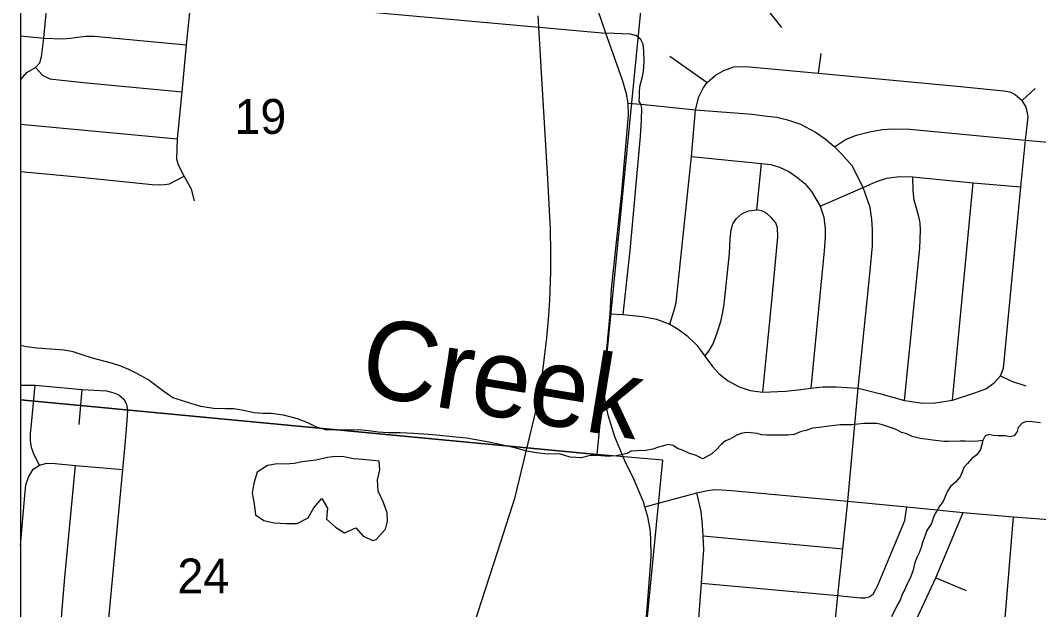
# Model space of a CAD drawing. Extents: x 0 to 34, y 0 to 22.
# Drawn here: x 1.912 to 3.134, y 16.316 to 17.023 of the extents above; entities that cross this region are included whole.
import ezdxf

# ---------------------------------------------------------------- set-up
doc = ezdxf.new("R2010")
doc.units = 0
for name, color, linetype in [('GM_X_City_Street', 7, 'Continuous'), ('GM_X_Corporation', 7, 'Continuous'), ('GM_X_County_Road', 7, 'Continuous'), ('GM_X_Minor_Lake', 7, 'Continuous'), ('GM_X_Minor_River', 7, 'Continuous'), ('GM_X_Minor_River_Text', 7, 'Continuous'), ('GM_X_Rail_Line', 7, 'Continuous'), ('GM_X_Section_Text', 7, 'Continuous')]:
    doc.layers.add(name, color=color, linetype=linetype)

msp = doc.modelspace()

# ---------------------------------------------------------------- linework, layer by layer
at = {"layer": 'GM_X_City_Street'}
for p, q in [((2.6913, 16.98), (2.7361, 16.9485)), ((2.8697, 16.9597), (2.8731, 16.9833)), ((3.1141, 16.927), (3.13, 16.9414)), ((1.9119, 16.8983), (2.1004, 16.8808)), ((2.7957, 16.7958), (2.8014, 16.8511)), ((3.0306, 16.5674), (3.0555, 16.8282)), ((1.9823, 16.5381), (1.986, 16.5803)), ((2.7314, 16.4048), (2.8989, 16.3891)), ((3.0105, 16.3541), (3.0471, 16.339))]:
    msp.add_line(p, q, dxfattribs=at)
for points in [[(2.8256, 17.0144), (2.8057, 17.0397), (2.7927, 17.0541), (2.7848, 17.0643), (2.7775, 17.0752), (2.7735, 17.0861), (2.7724, 17.097), (2.7742, 17.1209), (2.7788, 17.1692), (2.7815, 17.1984), (2.7824, 17.2213), (2.782, 17.2298), (2.7793, 17.2429), (2.7749, 17.2575), (2.7707, 17.2683), (2.7612, 17.286), (2.7527, 17.2976), (2.7471, 17.304), (2.7397, 17.3099), (2.729, 17.3149), (2.7152, 17.3176)], [(1.9119, 16.9515), (1.9196, 16.9603), (1.9301, 16.9665), (1.9352, 16.9719), (1.9372, 16.9792), (1.9401, 17.0018), (1.9462, 17.0651), (1.9467, 17.0701)], [(2.121, 16.8066), (2.1174, 16.8205), (2.1084, 16.836), (2.1016, 16.8491), (2.0995, 16.8563), (2.1004, 16.8808), (2.106, 16.9372), (2.1111, 16.9937), (2.1173, 17.0524), (2.1184, 17.0661)], [(2.0384, 17.0604), (2.0606, 17.0586), (2.1173, 17.0524), (2.343, 17.0322), (2.6147, 17.0077)], [(1.9119, 17.0045), (1.9401, 17.0018), (1.9627, 17.0008), (1.9721, 17.0017), (1.9802, 17.0027), (1.9907, 17.0039), (2.0004, 17.004), (2.1111, 16.9937)], [(2.6355, 16.6703), (2.6436, 16.7471), (2.6563, 16.8838), (2.6575, 16.9032), (2.6579, 16.9177), (2.6565, 16.9224), (2.6545, 16.9258), (2.6548, 16.9326), (2.6549, 16.9364), (2.6553, 16.9436), (2.6586, 16.9555), (2.6599, 16.9621), (2.6603, 16.9671), (2.6604, 16.9734), (2.6601, 16.9861), (2.6594, 16.9945), (2.6564, 17), (2.6513, 17.0045), (2.6443, 17.0065), (2.6147, 17.0077)], [(1.9301, 16.9665), (1.9386, 16.9571), (1.9472, 16.9527), (1.9873, 16.9484), (2.106, 16.9372)], [(2.7223, 16.9158), (2.7262, 16.9313), (2.7315, 16.9415), (2.7361, 16.9485), (2.746, 16.9571), (2.756, 16.9628), (2.7683, 16.9672), (2.7822, 16.9676), (2.8697, 16.9597), (3.0401, 16.9435), (3.0922, 16.9386), (3.0994, 16.9371), (3.106, 16.9341), (3.1141, 16.927)], [(3.0882, 16.5966), (3.0918, 16.6056), (3.0933, 16.622), (3.1127, 16.8233), (3.1184, 16.8792), (3.1208, 16.8999), (3.1214, 16.9074), (3.1208, 16.912), (3.1186, 16.9195), (3.1141, 16.927)], [(2.6415, 16.9235), (2.6565, 16.9224), (2.7223, 16.9158), (2.79, 16.9103), (2.8083, 16.9081), (2.8196, 16.9069), (2.8326, 16.9038), (2.848, 16.8985), (2.866, 16.8889), (2.8778, 16.881), (2.8881, 16.8721)], [(2.6915, 16.6584), (2.6967, 16.6753), (2.699, 16.6846), (2.7174, 16.8597), (2.7223, 16.9158)], [(2.8881, 16.8721), (2.8889, 16.8714), (2.9022, 16.8801), (2.9154, 16.8852), (2.9311, 16.8893), (2.9465, 16.8919), (2.9589, 16.8928), (2.9794, 16.8926), (3.1184, 16.8792), (3.1496, 16.8764)], [(2.8103, 16.1372), (2.8113, 16.1389), (2.8751, 16.2416), (2.8796, 16.2493), (2.8838, 16.2589), (2.8875, 16.276), (2.8931, 16.333), (2.8989, 16.3891), (2.9049, 16.4462), (2.9174, 16.5819), (2.9313, 16.7186), (2.934, 16.7443), (2.9345, 16.7527), (2.9348, 16.7723), (2.9339, 16.7843), (2.9317, 16.7986), (2.9235, 16.8227), (2.9101, 16.8483), (2.897, 16.8632), (2.8889, 16.8714)], [(2.7174, 16.8597), (2.8014, 16.8511), (2.8127, 16.8499), (2.8228, 16.8467), (2.834, 16.8417), (2.8433, 16.8353), (2.8532, 16.8271), (2.8613, 16.8179), (2.8717, 16.8003), (2.876, 16.7868), (2.8778, 16.7728), (2.8779, 16.7628), (2.8765, 16.7467), (2.8607, 16.5818)], [(1.9119, 16.8417), (1.9765, 16.8358), (2.0701, 16.8262), (2.0794, 16.8257), (2.0854, 16.826), (2.0907, 16.827), (2.1084, 16.836)], [(2.8717, 16.8003), (2.9235, 16.8227), (2.9396, 16.8297), (2.9517, 16.8337), (2.9672, 16.8357), (2.9832, 16.8351), (3.0555, 16.8282), (3.1127, 16.8233)], [(2.9729, 16.567), (2.9913, 16.7496), (2.9921, 16.7714), (2.992, 16.7797), (2.9902, 16.7878), (2.988, 16.796), (2.9847, 16.8074), (2.9836, 16.819), (2.9832, 16.8351)], [(2.7332, 16.6203), (2.7381, 16.6263), (2.7434, 16.6351), (2.7483, 16.648), (2.7526, 16.6618), (2.7546, 16.6708), (2.7566, 16.6825), (2.7628, 16.7434), (2.7639, 16.761), (2.7649, 16.7717), (2.7669, 16.7789), (2.7709, 16.7851), (2.7781, 16.7912), (2.7861, 16.7945), (2.7957, 16.7958)], [(2.8031, 16.5768), (2.8144, 16.6944), (2.8211, 16.7635), (2.8207, 16.774), (2.8186, 16.7803), (2.8131, 16.7866), (2.8079, 16.7912), (2.8024, 16.7941), (2.7957, 16.7958)], [(2.6199, 16.6708), (2.6355, 16.6703), (2.6587, 16.6676), (2.6754, 16.6644), (2.6915, 16.6584), (2.7015, 16.6524), (2.712, 16.6445), (2.7237, 16.6332), (2.7332, 16.6203), (2.7424, 16.6077), (2.7501, 16.5994), (2.7605, 16.5911), (2.7745, 16.5833), (2.7877, 16.5788), (2.8031, 16.5768), (2.8303, 16.5782), (2.8486, 16.5802), (2.8607, 16.5818), (2.8748, 16.5832), (2.8911, 16.5835), (2.9174, 16.5819), (2.9445, 16.5748), (2.9729, 16.567), (2.9923, 16.5641), (3.0073, 16.5639), (3.0306, 16.5674), (3.0576, 16.576), (3.0707, 16.5811), (3.0807, 16.5881), (3.0882, 16.5966)], [(3.0882, 16.5966), (3.1014, 16.5901), (3.1185, 16.5845)], [(1.9119, 16.5852), (1.9123, 16.5853), (1.9296, 16.5852), (1.986, 16.5803), (2.0154, 16.5785), (2.024, 16.5763), (2.0301, 16.5736), (2.0366, 16.568)], [(1.9348, 16.4894), (1.9283, 16.5019), (1.9254, 16.5107), (1.924, 16.5191), (1.9241, 16.5274), (1.9252, 16.5387), (1.9296, 16.5852)], [(1.9901, 15.9301), (2, 16.0388), (2.0032, 16.0719), (2.0147, 16.2007), (2.0176, 16.2342), (2.0174, 16.2504), (2.0164, 16.2703), (2.0165, 16.2881), (2.0348, 16.4843), (2.0375, 16.5136), (2.0395, 16.5378), (2.0406, 16.5484), (2.0409, 16.5555), (2.0396, 16.5621), (2.0366, 16.568)], [(1.9119, 16.3931), (1.9174, 16.453), (1.9185, 16.4656), (1.9217, 16.4748), (1.9273, 16.4845), (1.9348, 16.4894)], [(1.9119, 16.259), (1.9314, 16.2618), (1.9418, 16.2644), (1.9491, 16.2683), (1.9547, 16.2736), (1.9587, 16.281), (1.9601, 16.2897), (1.962, 16.3167), (1.9653, 16.3546), (1.9779, 16.4891)], [(1.9348, 16.4894), (1.9437, 16.4918), (1.9535, 16.4912), (1.9779, 16.4891), (2.0348, 16.4843)], [(2.6613, 16.4392), (2.7238, 16.4563), (2.7365, 16.4591), (2.7463, 16.4601), (2.7539, 16.4597), (2.7654, 16.4589), (2.7874, 16.4569), (2.9049, 16.4462), (2.9759, 16.4395), (3.0434, 16.4327), (3.1038, 16.4274), (3.1408, 16.4245), (3.1532, 16.4228), (3.1606, 16.4208), (3.1756, 16.4168), (3.405, 16.3956), (3.4416, 16.3923), (3.4637, 16.3923), (3.5, 16.3912), (3.5347, 16.388), (3.6039, 16.383)], [(2.7243, 16.2806), (2.7249, 16.2895), (2.7294, 16.3479), (2.7311, 16.3723), (2.732, 16.388), (2.7314, 16.4048), (2.7304, 16.4173), (2.7289, 16.4338), (2.7238, 16.4563)], [(2.7294, 16.3479), (2.8931, 16.333), (2.9203, 16.3302), (2.9258, 16.3304), (2.9305, 16.3314), (2.9356, 16.3348), (2.9381, 16.3397), (2.9413, 16.3464), (2.9733, 16.4229), (2.9759, 16.4395)], [(2.8381, 16.0606), (2.8689, 16.1125), (2.9269, 16.2052), (2.9536, 16.2499), (2.9864, 16.302), (3.0105, 16.3541), (3.0434, 16.4327)], [(3.0573, 15.9654), (3.0618, 15.9752), (3.0642, 15.9847), (3.0676, 16.0257), (3.0859, 16.2088), (3.1038, 16.4274)]]:
    msp.add_lwpolyline(points, dxfattribs=at)
at = {"layer": 'GM_X_Corporation'}
for points in [[(1.9119, 21.1059), (1.9119, 14.3059)], [(1.9119, 21.1059), (1.9119, 14.3059)], [(1.9119, 17.5586), (1.9119, 14.3059)]]:
    msp.add_lwpolyline(points, dxfattribs=at)
for points in [[(1.9119, 17.5883), (1.9119, 16.5679), (2.6041, 16.5022), (2.7042, 17.5166)], [(1.9119, 16.5679), (1.9119, 16.2138), (2.6486, 16.1444), (2.6831, 16.4952), (2.6041, 16.5022)]]:
    msp.add_lwpolyline(points, close=True, dxfattribs=at)
at = {"layer": 'GM_X_County_Road'}
for points in [[(2.6593, 16.4462), (2.6484, 16.4718), (2.6373, 16.4947), (2.6253, 16.5232), (2.6173, 16.5495), (2.6133, 16.5694), (2.6127, 16.5947), (2.6199, 16.6708), (2.6214, 16.7007), (2.6339, 16.8168), (2.6419, 16.9094), (2.6415, 16.9235), (2.6392, 16.9349), (2.6344, 16.9513), (2.6147, 17.0077), (2.605, 17.0355)], [(2.6501, 16.1403), (2.6605, 16.2708), (2.6691, 16.3795), (2.6684, 16.4015), (2.6676, 16.4125), (2.6651, 16.4272), (2.6613, 16.4392), (2.6597, 16.4453), (2.6593, 16.4462)]]:
    msp.add_lwpolyline(points, dxfattribs=at)
at = {"layer": 'GM_X_Minor_Lake'}
for points in [[(2.3426, 16.4942), (2.3229, 16.496), (2.3119, 16.497), (2.3002, 16.4995), (2.2903, 16.4997), (2.2804, 16.4987), (2.2667, 16.4955), (2.25, 16.4932), (2.2405, 16.4915), (2.2302, 16.4906), (2.22, 16.4911), (2.2086, 16.4891), (2.1959, 16.4809), (2.1922, 16.4677), (2.1901, 16.4556), (2.1925, 16.443), (2.1941, 16.4296), (2.2039, 16.423), (2.2163, 16.4201), (2.2307, 16.4194), (2.244, 16.4195), (2.2574, 16.4261), (2.2641, 16.4382), (2.2738, 16.4494), (2.2804, 16.4379), (2.2794, 16.4246), (2.2902, 16.4152), (2.3011, 16.4082), (2.3145, 16.4144), (2.3234, 16.4043), (2.335, 16.3991)], [(2.335, 16.3991), (2.3388, 16.4002), (2.3501, 16.4125), (2.3526, 16.4224), (2.352, 16.4323), (2.3473, 16.4453), (2.3415, 16.458), (2.3406, 16.4717), (2.3435, 16.4838), (2.3426, 16.4942)]]:
    msp.add_lwpolyline(points, dxfattribs=at)
at = {"layer": 'GM_X_Minor_River'}
for points in [[(2.5719, 16.499), (2.5588, 16.5028), (2.5451, 16.5025), (2.5311, 16.5042), (2.5198, 16.5061), (2.5055, 16.5101), (2.4874, 16.5141), (2.4761, 16.5164), (2.4652, 16.5184), (2.4475, 16.5217), (2.4305, 16.5234), (2.4115, 16.5252), (2.4017, 16.526), (2.3839, 16.5274), (2.3676, 16.528), (2.3532, 16.5281), (2.3415, 16.5289), (2.3298, 16.5305), (2.318, 16.5317), (2.3059, 16.5313), (2.2919, 16.5319), (2.2797, 16.5315), (2.2673, 16.535), (2.2569, 16.5403), (2.2445, 16.545), (2.2276, 16.5494), (2.2125, 16.5514), (2.203, 16.5514), (2.1924, 16.5522), (2.1777, 16.5554), (2.1679, 16.5569), (2.158, 16.5568), (2.1436, 16.5574), (2.1285, 16.5598), (2.1165, 16.5633), (2.1052, 16.5671), (2.0947, 16.5702), (2.084, 16.5778), (2.0648, 16.5921), (2.0518, 16.5994), (2.042, 16.604), (2.0323, 16.6081), (2.0211, 16.6116), (1.9985, 16.6177), (1.9873, 16.6215), (1.9753, 16.6254), (1.9643, 16.6273), (1.948, 16.6287), (1.9318, 16.6296), (1.9193, 16.6312), (1.9119, 16.6328)], [(3.1363, 16.54), (3.1264, 16.5415), (3.1195, 16.5419), (3.1142, 16.5396), (3.1096, 16.5347), (3.1081, 16.5297), (3.1047, 16.5244), (3.0994, 16.5233), (3.0944, 16.5244), (3.0853, 16.5244), (3.0796, 16.5248), (3.0747, 16.5263), (3.0697, 16.5244), (3.0671, 16.5191), (3.0579, 16.5176), (3.0458, 16.5183), (3.0397, 16.5183), (3.026, 16.5176), (3.0207, 16.5176), (3.0066, 16.5195), (3.0013, 16.5202), (2.9918, 16.5214), (2.9823, 16.5237), (2.9758, 16.5271), (2.9693, 16.5286), (2.964, 16.5316), (2.9587, 16.5339), (2.945, 16.5381), (2.9397, 16.5392), (2.9245, 16.5392), (2.9093, 16.5377), (2.8956, 16.5377), (2.8823, 16.5362), (2.8705, 16.5347), (2.8625, 16.5339), (2.8549, 16.5309), (2.8488, 16.5297), (2.8404, 16.5263), (2.8328, 16.5255), (2.8206, 16.5255), (2.8073, 16.5255), (2.8013, 16.5259), (2.7963, 16.5274), (2.7887, 16.5282), (2.7834, 16.5286), (2.7765, 16.5274), (2.7716, 16.5252), (2.7632, 16.5206), (2.7583, 16.5187), (2.753, 16.5142), (2.7473, 16.5081), (2.7416, 16.5028), (2.7309, 16.4971), (2.7229, 16.5009), (2.7142, 16.5039), (2.7066, 16.5073), (2.7005, 16.5092), (2.6952, 16.513), (2.6891, 16.5142), (2.6838, 16.5126), (2.6777, 16.5111), (2.6708, 16.5085), (2.6625, 16.5069), (2.6522, 16.5066), (2.645, 16.5062), (2.64, 16.5035), (2.6347, 16.502), (2.6271, 16.5005), (2.6206, 16.5001), (2.6137, 16.5001), (2.6086, 16.5005), (2.6023, 16.5009), (2.5965, 16.5009), (2.591, 16.4997), (2.5855, 16.4982), (2.5719, 16.499)], [(3.0671, 16.5191), (3.0644, 16.5081), (3.0598, 16.5016), (3.0537, 16.4975), (3.0488, 16.4914), (3.0442, 16.4865), (3.0423, 16.4808), (3.0397, 16.4755), (3.0344, 16.469), (3.0283, 16.4637), (3.0245, 16.458), (3.0218, 16.4519), (3.0195, 16.4458), (3.015, 16.4401), (3.0115, 16.4337), (3.0081, 16.428), (3.0055, 16.4196), (2.9998, 16.4109), (2.9979, 16.4052), (2.9948, 16.3965), (2.9929, 16.3908), (2.9906, 16.3843), (2.9883, 16.3794), (2.9853, 16.3726), (2.983, 16.3623), (2.98, 16.354), (2.9762, 16.3471), (2.9735, 16.3403), (2.9705, 16.3354), (2.9678, 16.3274), (2.964, 16.3205), (2.9575, 16.3076)]]:
    msp.add_lwpolyline(points, dxfattribs=at)
at = {"layer": 'GM_X_Rail_Line'}
for points in [[(2.533, 17.0284), (2.5371, 16.9604), (2.5445, 16.8328), (2.5467, 16.7951), (2.5476, 16.7735), (2.5481, 16.7438), (2.548, 16.7212), (2.5469, 16.6874), (2.5456, 16.669), (2.5433, 16.6421), (2.5394, 16.6091), (2.534, 16.5696)], [(2.1167, 15.2597), (2.2383, 15.6396), (2.3189, 15.8927), (2.4132, 16.1654), (2.4851, 16.3863), (2.5056, 16.4511), (2.534, 16.5691)]]:
    msp.add_lwpolyline(points, dxfattribs=at)

# ---------------------------------------------------------------- texts
at = {"layer": 'GM_X_Minor_River_Text'}
msp.add_text('Creek', height=0.09469, rotation=350.6675, dxfattribs=at).set_placement((2.3164, 16.575))
at = {"layer": 'GM_X_Section_Text'}
for s, p in [('19', (2.1688, 16.8868)), ('24', (2.1004, 16.3355))]:
    msp.add_text(s, height=0.04186, rotation=0, dxfattribs=at).set_placement(p)

doc.saveas('drawing.dxf')
